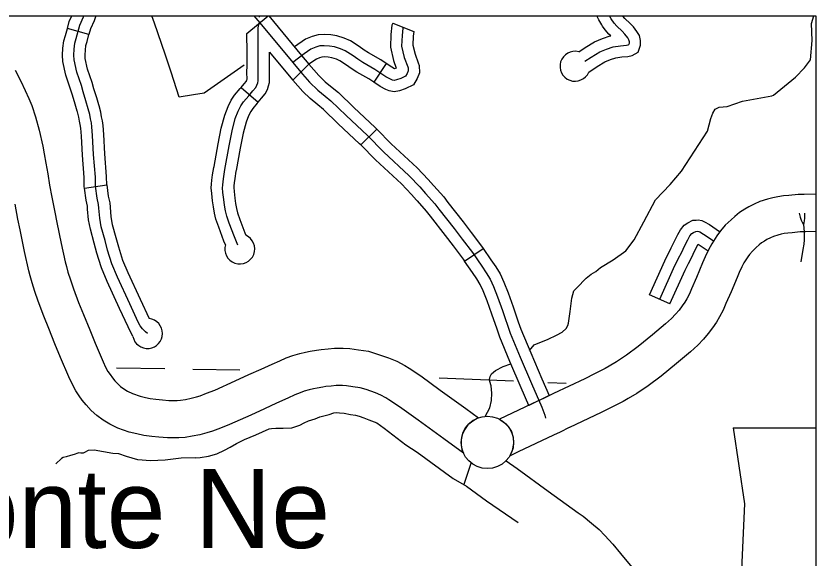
# Model space of a CAD drawing. Extents: x 670147 to 673275, y 705573 to 707613.
# Drawn here: x 672115.2 to 672221.9, y 706616.9 to 706689.4 of the extents above; entities that cross this region are included whole.
import ezdxf

# ---------------------------------------------------------------- set-up
doc = ezdxf.new("R2010")
doc.units = 0
for name, color, linetype in [('10', 7, 'Continuous'), ('21', 7, 'Continuous'), ('24', 7, 'Continuous'), ('31', 7, 'Continuous'), ('32', 7, 'Continuous'), ('33', 7, 'Continuous'), ('35', 7, 'Continuous'), ('5', 7, 'Continuous'), ('6', 7, 'Continuous'), ('R_NoPlot', 7, 'Continuous')]:
    doc.layers.add(name, color=color, linetype=linetype)

msp = doc.modelspace()

# ---------------------------------------------------------------- linework, layer by layer
at = {"layer": '10'}
msp.add_line((672186.91, 706638.92), (672186.89, 706638.91), dxfattribs=at)
for points in [[(672115.05, 706682.13), (672115.81, 706680.63), (672116.4, 706679.41), (672116.86, 706678.32), (672117.25, 706677.39), (672117.76, 706675.89), (672118.25, 706674.09), (672118.73, 706671.95), (672118.91, 706670.94), (672119.14, 706669.67), (672119.4, 706668.25), (672119.65, 706666.75), (672119.96, 706665.16), (672120.33, 706663.15), (672120.61, 706661.76), (672121.17, 706658.94), (672121.74, 706656.49), (672121.88, 706655.9), (672122.09, 706655.14), (672122.43, 706654.12), (672122.84, 706652.9), (672123.52, 706651.06), (672124.16, 706649.46), (672124.99, 706647.44), (672125.72, 706645.64), (672126.78, 706643.16), (672127.11, 706642.45), (672127.43, 706641.87), (672127.72, 706641.44), (672128.03, 706641), (672128.33, 706640.62), (672128.69, 706640.23), (672129.1, 706639.86), (672129.54, 706639.53), (672130.05, 706639.23), (672130.7, 706638.92), (672131.71, 706638.55), (672132.44, 706638.37), (672133.05, 706638.23), (672133.83, 706638.14), (672134.69, 706638.05), (672135.56, 706637.98), (672136.66, 706637.98), (672137.12, 706638.02), (672137.79, 706638.12), (672138.52, 706638.28), (672139.27, 706638.47), (672139.76, 706638.62), (672140.6, 706638.94), (672141.68, 706639.38), (672144.43, 706640.6), (672146.25, 706641.43), (672147.87, 706642.16), (672149.37, 706642.84), (672150.37, 706643.3), (672151.23, 706643.67), (672152.09, 706643.98), (672153.05, 706644.25), (672153.79, 706644.42), (672154.42, 706644.56), (672155.26, 706644.7), (672155.88, 706644.8), (672156.8, 706644.88), (672157.66, 706644.95), (672158.82, 706644.97), (672159.71, 706644.93), (672160.88, 706644.77), (672162.21, 706644.55), (672163.42, 706644.19), (672164.88, 706643.67), (672165.97, 706643.24), (672167.06, 706642.64), (672167.62, 706642.29), (672169.19, 706641.26), (672171.77, 706639.38), (672175.18, 706636.89), (672176.88, 706635.67), (672176.16, 706635.32), (672175.48, 706634.74), (672175.01, 706634.08), (672174.69, 706633.4), (672174.58, 706632.74), (672174.58, 706632.04), (672174.67, 706631.42), (672174.87, 706630.96)], [(672221.93, 706665.57), (672220.35, 706665.51), (672219.55, 706665.49), (672218.3, 706665.38), (672217.58, 706665.32), (672216.82, 706665.21), (672216.15, 706665.07), (672215.44, 706664.88), (672214.43, 706664.55), (672213.67, 706664.21), (672212.97, 706663.84), (672212.44, 706663.53), (672211.72, 706663.09), (672211.1, 706662.55), (672210.6, 706662.13), (672209.83, 706661.39), (672209.17, 706660.63), (672208.7, 706660), (672208.01, 706658.9), (672207.57, 706658.1), (672207.13, 706657.17), (672206.78, 706656.37), (672205.98, 706654.43), (672205.33, 706652.92), (672205.03, 706652.22), (672204.68, 706651.57), (672204.42, 706651.13), (672204.07, 706650.63), (672203.65, 706650.07), (672203.18, 706649.52), (672202.63, 706648.94), (672201.85, 706648.21), (672200.13, 706646.77), (672198.19, 706645.19), (672196.63, 706644.02), (672195.32, 706643.14), (672194.32, 706642.55), (672193.8, 706642.24), (672192.37, 706641.53), (672191.06, 706640.86), (672186.91, 706638.92)], [(672174.87, 706630.96), (672172.25, 706632.84), (672168.82, 706635.35), (672166.35, 706637.15), (672164.92, 706638.08), (672164.53, 706638.33), (672163.83, 706638.71), (672163.12, 706638.99), (672161.88, 706639.43), (672161.08, 706639.67), (672160.13, 706639.82), (672159.25, 706639.95), (672158.74, 706639.97), (672157.9, 706639.96), (672157.22, 706639.9), (672156.51, 706639.84), (672156.09, 706639.77), (672155.36, 706639.64), (672154.86, 706639.54), (672154.29, 706639.41), (672153.63, 706639.22), (672153.07, 706639.02), (672152.39, 706638.72), (672151.44, 706638.29), (672149.94, 706637.61), (672148.32, 706636.87), (672146.48, 706636.04), (672143.64, 706634.78), (672142.44, 706634.29), (672141.37, 706633.89), (672140.63, 706633.66), (672139.68, 706633.41), (672138.69, 706633.2), (672137.72, 706633.05), (672136.87, 706632.98), (672135.36, 706632.98), (672134.24, 706633.07), (672133.28, 706633.17), (672132.2, 706633.3), (672131.27, 706633.51), (672130.25, 706633.76), (672128.75, 706634.3), (672127.68, 706634.82), (672126.77, 706635.36), (672125.95, 706635.98), (672125.18, 706636.65), (672124.51, 706637.38), (672124.01, 706638.02), (672123.61, 706638.59), (672123.16, 706639.26), (672122.64, 706640.2), (672122.21, 706641.13), (672121.11, 706643.72), (672120.36, 706645.55), (672119.53, 706647.59), (672118.86, 706649.26), (672118.13, 706651.23), (672117.68, 706652.55), (672117.31, 706653.69), (672117.05, 706654.63), (672116.88, 706655.32), (672116.28, 706657.89), (672115.7, 706660.79), (672115.42, 706662.2), (672115.04, 706664.23)], [(672221.93, 706660.56), (672220.51, 706660.52), (672219.83, 706660.5), (672218.73, 706660.4), (672218.16, 706660.35), (672217.7, 706660.28), (672217.3, 706660.2), (672216.86, 706660.09), (672216.25, 706659.88), (672215.84, 706659.7), (672215.39, 706659.47), (672215.04, 706659.25), (672214.68, 706659.03), (672214.36, 706658.76), (672213.96, 706658.42), (672213.45, 706657.93), (672213.07, 706657.49), (672212.83, 706657.17), (672212.32, 706656.36), (672212.02, 706655.82), (672211.68, 706655.1), (672211.39, 706654.42), (672210.59, 706652.49), (672209.92, 706650.93), (672209.53, 706650.04), (672209.05, 706649.15), (672208.64, 706648.43), (672208.1, 706647.67), (672207.55, 706646.94), (672206.9, 706646.17), (672206.15, 706645.39), (672205.18, 706644.47), (672203.31, 706642.91), (672201.27, 706641.25), (672199.53, 706639.95), (672198, 706638.92), (672196.87, 706638.25), (672196.18, 706637.84), (672194.61, 706637.06), (672193.26, 706636.37), (672189.03, 706634.39)], [(672186.89, 706638.91), (672185.63, 706638.31), (672184.76, 706637.88), (672179.68, 706635.48), (672180.36, 706635), (672180.84, 706634.52), (672181.28, 706633.83), (672181.52, 706633.05), (672181.58, 706632.23), (672181.4, 706631.3), (672181.07, 706630.58)], [(672181.07, 706630.58), (672182.24, 706631.16), (672186.92, 706633.37), (672187.81, 706633.81), (672189.05, 706634.4)], [(672180.57, 706629.93), (672182.03, 706628.88), (672186.19, 706625.85), (672190.19, 706622.97), (672190.87, 706622.51), (672191.98, 706621.6), (672192.99, 706620.73), (672193.76, 706619.94), (672194.8, 706618.79), (672195.84, 706617.54), (672197.36, 706615.72)]]:
    msp.add_lwpolyline(points, dxfattribs=at)
at = {"layer": '21'}
for p, q in [((672210.86, 706634.34), (672212.38, 706624.19)), ((672212.38, 706624.19), (672211.71, 706608.8))]:
    msp.add_line(p, q, dxfattribs=at)
msp.add_lwpolyline([(672210.86, 706634.34), (672221.93, 706634.34)], dxfattribs=at)
at = {"layer": '24'}
msp.add_circle((672178.07, 706632.38), 3.5, dxfattribs=at)
at = {"layer": '31'}
for p, q in [((672145.97, 706687), (672148.83, 706689.36)), ((672124.9, 706686.89), (672122.01, 706687.68)), ((672152.12, 706680.77), (672154.25, 706682.9)), ((672145.2, 706679.81), (672147.46, 706677.84)), ((672163.31, 706674.24), (672161.19, 706672.12)), ((672124.29, 706666.37), (672127.27, 706666.78)), ((672124.29, 706666.37), (672124.29, 706666.37)), ((672175.03, 706656.6), (672177.5, 706658.29))]:
    msp.add_line(p, q, dxfattribs=at)
for points in [[(672122.01, 706687.68), (672122.26, 706688.62), (672122.59, 706689.36)], [(672132.71, 706646.93), (672132.43, 706647.15), (672132.04, 706647.56), (672131.72, 706647.95), (672131.48, 706648.45), (672130.36, 706650.89), (672128.71, 706654.46), (672127.97, 706656.22), (672127.38, 706658.07), (672127.04, 706659.37), (672126.54, 706661.18), (672126.34, 706662.33), (672126.21, 706663.68), (672126.18, 706664.16), (672125.99, 706665.01), (672125.77, 706666.64), (672125.75, 706667.83), (672125.51, 706670.87), (672125.38, 706673.4), (672125.29, 706674.55), (672125.22, 706675.1), (672125.11, 706675.6), (672125.01, 706676.18), (672124.81, 706676.94), (672124.5, 706678.01), (672124.13, 706679.21), (672123.88, 706680.05), (672123.27, 706681.87), (672122.92, 706683.48), (672122.89, 706684.14), (672122.92, 706684.92), (672123.02, 706685.73), (672123.2, 706686.34), (672123.68, 706688.12), (672124.18, 706689.25), (672124.22, 706689.36)], [(672125.8, 706689.36), (672125.58, 706688.71), (672125.1, 706687.62), (672124.9, 706686.89)], [(672148.9, 706689.36), (672153.25, 706684.1), (672154.25, 706682.9)], [(672191.1, 706683.32), (672191.91, 706683.86), (672193.07, 706684.55), (672193.98, 706684.94), (672194.84, 706685.24), (672195.85, 706685.38), (672196.62, 706685.44), (672196.87, 706685.49), (672196.97, 706685.54), (672197.03, 706685.72), (672197.03, 706685.92), (672196.97, 706686.16), (672196.8, 706686.44), (672196.4, 706686.94), (672196.07, 706687.34), (672195.36, 706687.99), (672194.98, 706688.42), (672194.6, 706688.97), (672194.38, 706689.36)], [(672191.6, 706681.86), (672192.71, 706682.59), (672193.75, 706683.21), (672194.52, 706683.54), (672195.2, 706683.77), (672196.01, 706683.89), (672196.81, 706683.95), (672197.38, 706684.06), (672198.21, 706684.52), (672198.53, 706685.47), (672198.53, 706686.1), (672198.37, 706686.75), (672198.03, 706687.3), (672197.56, 706687.89), (672197.15, 706688.37), (672196.43, 706689.04), (672196.17, 706689.34), (672196.16, 706689.36)], [(672193.45, 706688), (672193.33, 706688.18), (672192.95, 706688.84), (672192.68, 706689.36)], [(672144.75, 706658.74), (672144.3, 706659.83), (672143.62, 706661.66), (672143.29, 706662.62), (672143.11, 706663.34), (672142.98, 706664.08), (672142.89, 706664.84), (672142.78, 706665.77), (672142.73, 706666.41), (672142.75, 706666.77), (672142.79, 706667.25), (672142.89, 706667.89), (672143.04, 706668.86), (672143.61, 706671.99), (672144.01, 706674.01), (672144.43, 706675.64), (672144.83, 706676.65), (672145.18, 706677.35), (672145.54, 706677.89), (672146.22, 706678.7), (672146.78, 706679.34), (672147.16, 706679.8), (672147.32, 706680.11), (672147.42, 706680.42), (672147.48, 706680.69), (672147.5, 706681.06), (672147.47, 706681.69), (672147.5, 706682.87), (672147.5, 706684.51), (672147.47, 706687.68), (672147.54, 706688.07), (672147.71, 706688.44)], [(672147.71, 706688.44), (672152.09, 706683.14), (672153.4, 706681.58), (672154.35, 706680.5), (672155.43, 706679.44), (672156.42, 706678.63), (672157.19, 706678), (672159.21, 706676.05), (672162.06, 706673.37), (672164.21, 706671.21), (672167.65, 706667.98), (672169.07, 706666.51), (672169.81, 706665.65), (672171.08, 706664.24), (672171.61, 706663.53), (672173.63, 706660.96), (672174.71, 706659.54), (672176.07, 706657.74), (672177.31, 706655.92), (672177.92, 706655.04), (672178.44, 706654.18), (672178.89, 706653.22), (672179.44, 706651.84), (672180.08, 706650), (672181.13, 706646.99), (672182.47, 706643.77), (672183.97, 706640.27), (672185.35, 706637.07), (672185.72, 706636.03), (672185.84, 706635.63)], [(672190.27, 706684.57), (672191.11, 706685.13), (672192.39, 706685.89), (672193.44, 706686.34), (672194.48, 706686.7), (672194.53, 706686.71), (672194.28, 706686.94), (672193.79, 706687.5), (672193.45, 706688)], [(672123.33, 706676.64), (672123.06, 706677.58), (672122.69, 706678.78), (672122.45, 706679.6), (672121.83, 706681.47), (672121.43, 706683.27), (672121.38, 706684.14), (672121.43, 706685.04), (672121.54, 706686.04), (672121.76, 706686.76), (672122.01, 706687.68)], [(672145.2, 706679.81), (672145.63, 706680.31), (672145.9, 706680.63), (672145.92, 706680.68), (672145.97, 706680.83), (672145.99, 706680.9), (672146, 706681.06), (672145.97, 706681.68), (672146, 706682.88), (672146, 706684.5), (672145.97, 706687)], [(672126.21, 706677.48), (672125.93, 706678.44), (672125.56, 706679.64), (672125.32, 706680.49), (672124.72, 706682.27), (672124.41, 706683.68), (672124.39, 706684.15), (672124.42, 706684.8), (672124.49, 706685.43), (672124.64, 706685.93), (672124.9, 706686.89)], [(672147.46, 706677.84), (672147.92, 706678.36), (672148.42, 706678.97), (672148.71, 706679.53), (672148.86, 706680.02), (672148.98, 706680.48), (672149, 706681.05), (672148.98, 706681.7), (672149, 706682.85), (672149, 706684.52)], [(672149, 706684.52), (672150.94, 706682.18), (672152.12, 706680.77)], [(672154.25, 706682.9), (672155.56, 706681.42), (672156.43, 706680.55), (672157.37, 706679.79), (672158.19, 706679.12), (672160.24, 706677.13), (672163.11, 706674.44), (672163.31, 706674.24)], [(672161.19, 706672.12), (672161.02, 706672.29), (672158.17, 706674.96), (672156.19, 706676.88), (672155.46, 706677.47), (672154.42, 706678.32), (672153.45, 706679.29), (672152.12, 706680.77)], [(672141.59, 706669.23), (672142.13, 706672.27), (672142.55, 706674.35), (672143.01, 706676.1), (672143.46, 706677.26), (672143.88, 706678.1), (672144.34, 706678.79), (672145.08, 706679.68), (672145.2, 706679.81)], [(672127.27, 706666.76), (672127.25, 706667.9), (672127.01, 706670.96), (672126.88, 706673.5), (672126.78, 706674.71), (672126.69, 706675.37), (672126.58, 706675.89), (672126.48, 706676.49), (672126.25, 706677.34), (672126.21, 706677.48)], [(672147.46, 706677.84), (672147.36, 706677.73), (672146.75, 706677), (672146.48, 706676.59), (672146.2, 706676.03), (672145.86, 706675.17), (672145.47, 706673.68), (672145.08, 706671.71), (672144.54, 706668.7)], [(672124.29, 706666.37), (672124.27, 706666.53), (672124.25, 706667.76), (672124.02, 706670.77), (672123.89, 706673.3), (672123.8, 706674.39), (672123.74, 706674.84), (672123.63, 706675.32), (672123.54, 706675.86), (672123.37, 706676.53), (672123.33, 706676.64)], [(672163.31, 706674.24), (672165.25, 706672.29), (672168.71, 706669.05), (672170.18, 706667.52), (672170.87, 706666.72)], [(672161.19, 706672.12), (672163.16, 706670.14), (672166.6, 706666.91), (672167.96, 706665.49), (672168.6, 706664.76)], [(672143.1, 706658.8), (672142.9, 706659.28), (672142.21, 706661.15), (672141.85, 706662.2), (672141.64, 706663.02), (672141.5, 706663.86), (672141.4, 706664.67), (672141.28, 706665.63), (672141.22, 706666.4), (672141.25, 706666.88), (672141.3, 706667.43), (672141.4, 706668.12), (672141.57, 706669.11), (672141.59, 706669.23)], [(672144.54, 706668.7), (672144.52, 706668.61), (672144.37, 706667.66), (672144.28, 706667.08), (672144.25, 706666.66), (672144.23, 706666.43), (672144.27, 706665.92), (672144.38, 706665.02), (672144.46, 706664.3), (672144.58, 706663.65), (672144.73, 706663.05), (672145.03, 706662.16), (672145.69, 706660.38), (672145.83, 706660.06)], [(672127.27, 706666.78), (672127.47, 706665.27), (672127.67, 706664.37), (672127.71, 706663.81), (672127.83, 706662.53), (672128.01, 706661.51), (672128.49, 706659.76), (672128.82, 706658.49), (672129.38, 706656.73)], [(672170.87, 706666.72), (672170.93, 706666.65), (672172.24, 706665.19), (672172.8, 706664.45), (672174.82, 706661.87), (672175.9, 706660.44), (672177.29, 706658.61), (672177.5, 706658.29)], [(672126.52, 706655.82), (672125.94, 706657.66), (672125.59, 706658.98), (672125.08, 706660.85), (672124.85, 706662.13), (672124.72, 706663.56), (672124.69, 706663.95), (672124.52, 706664.75), (672124.29, 706666.37)], [(672168.6, 706664.76), (672168.68, 706664.66), (672169.92, 706663.28), (672170.42, 706662.62), (672172.44, 706660.04), (672173.51, 706658.63), (672174.85, 706656.86), (672175.03, 706656.6)], [(672177.5, 706658.29), (672178.54, 706656.77), (672179.18, 706655.85), (672179.76, 706654.9), (672180.27, 706653.81), (672180.84, 706652.36), (672181.5, 706650.49), (672182.2, 706648.47)], [(672129.38, 706656.73), (672129.38, 706656.74), (672130.08, 706655.07), (672131.72, 706651.52), (672132.92, 706648.92)], [(672179.37, 706647.49), (672178.67, 706649.5), (672178.03, 706651.31), (672177.52, 706652.63), (672177.12, 706653.47), (672176.66, 706654.22), (672176.07, 706655.07), (672175.03, 706656.6)], [(672130.75, 706646.52), (672130.13, 706647.81), (672128.99, 706650.26), (672127.34, 706653.86), (672126.56, 706655.7), (672126.52, 706655.82)], [(672186.31, 706638.63), (672183.6, 706637.33), (672182.6, 706639.68), (672181.08, 706643.19), (672179.73, 706646.45), (672179.37, 706647.49)], [(672182.2, 706648.47), (672182.54, 706647.52), (672183.85, 706644.35), (672185.35, 706640.86), (672186.31, 706638.63)]]:
    msp.add_lwpolyline(points, dxfattribs=at)
for centre, start, end in [((672189.76, 706682.64), 75.34, 337.0929), ((672145.02, 706658.23), 163.4625, 66.1741), ((672132.71, 706646.93), 191.8762, 83.8651)]:
    msp.add_arc(centre, 2, start, end, dxfattribs=at)
at = {"layer": '32'}
for p, q in [((672165.45, 706688.42), (672168.25, 706687.29)), ((672164.58, 706683), (672162.9, 706680.51)), ((672167.44, 706682.57), (672167.49, 706682.42)), ((672202.44, 706650.88), (672199.71, 706652.11))]:
    msp.add_line(p, q, dxfattribs=at)
for points in [[(672165.45, 706688.42), (672165.32, 706688.11), (672165.19, 706686.88), (672165.12, 706685.2), (672165.53, 706683.4), (672165.91, 706682.39), (672165.69, 706682.31), (672165.31, 706682.51), (672164.58, 706683)], [(672168.25, 706687.29), (672168.18, 706686.65), (672168.14, 706685.48), (672168.42, 706684.25), (672168.85, 706683.09), (672168.97, 706682.73), (672169.03, 706681.77), (672168.7, 706680.99), (672168.2, 706680.17), (672167.11, 706679.63), (672166.35, 706679.36), (672165.61, 706679.23), (672164.96, 706679.36), (672164.5, 706679.55), (672163.77, 706679.93), (672162.9, 706680.51)], [(672166.84, 706687.86), (672166.79, 706687.74), (672166.68, 706686.77), (672166.63, 706685.34), (672166.98, 706683.83), (672167.44, 706682.57)], [(672164.58, 706683), (672163.85, 706683.49), (672162.22, 706684.42), (672161.62, 706684.81), (672160.98, 706685.28), (672159.79, 706686.03), (672158.97, 706686.39), (672157.99, 706686.69), (672157.18, 706686.82), (672156.33, 706686.89), (672155.49, 706686.84), (672154.68, 706686.62), (672153.8, 706686.25), (672152.31, 706685.23)], [(672167.49, 706682.42), (672167.51, 706682.03), (672167.37, 706681.68), (672167.15, 706681.32), (672166.53, 706681.02), (672165.96, 706680.81), (672165.63, 706680.75), (672165.4, 706680.8), (672165.13, 706680.91), (672164.54, 706681.22), (672163.06, 706682.22), (672161.44, 706683.14), (672160.76, 706683.58), (672160.14, 706684.04), (672159.08, 706684.7), (672158.45, 706684.99), (672157.65, 706685.22), (672157, 706685.33), (672156.31, 706685.38), (672155.72, 706685.35), (672155.17, 706685.2), (672154.52, 706684.93), (672153.6, 706684.29), (672152.09, 706683.14)], [(672162.9, 706680.51), (672162.27, 706680.94), (672160.66, 706681.85), (672159.9, 706682.35), (672159.29, 706682.8), (672158.37, 706683.37), (672157.92, 706683.58), (672157.32, 706683.76), (672156.83, 706683.84), (672156.29, 706683.88), (672155.96, 706683.86), (672155.65, 706683.78), (672155.25, 706683.61), (672154.26, 706682.9)], [(672219.69, 706662.99), (672219.84, 706662.48), (672219.96, 706662.08), (672220.03, 706661.9), (672220.12, 706661.7), (672220.27, 706661.48), (672220.34, 706661.7), (672220.41, 706662), (672220.44, 706662.34), (672220.45, 706662.65), (672220.43, 706663.01)], [(672199.71, 706652.11), (672201.74, 706656.65), (672202.06, 706657.3), (672202.27, 706657.69), (672202.62, 706658.37), (672203.08, 706659.36), (672203.49, 706660.14), (672203.85, 706660.79), (672204.34, 706661.4), (672204.82, 706661.74), (672205.51, 706662.06), (672205.96, 706662.08)], [(672205.96, 706662.08), (672206.19, 706662.1), (672206.69, 706662.02), (672207.07, 706661.86), (672207.73, 706661.49), (672209.06, 706660.57)], [(672220.27, 706661.48), (672220.37, 706660.5), (672220.37, 706659.91), (672220.36, 706659.43), (672220.3, 706658.87), (672220.19, 706658.15), (672219.89, 706656.5)], [(672201.07, 706651.5), (672203.1, 706656.01), (672203.39, 706656.61), (672203.6, 706656.98), (672203.97, 706657.72), (672204.43, 706658.7), (672204.81, 706659.43), (672205.11, 706659.96), (672205.38, 706660.3), (672205.57, 706660.44), (672205.88, 706660.58), (672206.11, 706660.59), (672206.28, 706660.56), (672206.42, 706660.51), (672206.93, 706660.22), (672208.21, 706659.34)], [(672202.44, 706650.88), (672204.46, 706655.38), (672204.72, 706655.92), (672204.92, 706656.28), (672205.32, 706657.06), (672205.77, 706658.03), (672206.22, 706658.88)], [(672206.22, 706658.88), (672207.52, 706657.99)]]:
    msp.add_lwpolyline(points, dxfattribs=at)
at = {"layer": '33'}
msp.add_lwpolyline([(672146.89, 706689.36), (672147.71, 706688.44)], dxfattribs=at)
at = {"layer": '35'}
for points in [[(672216.05, 706678.67), (672216.27, 706678.79), (672219.2, 706681.19), (672220.38, 706682.42), (672221.18, 706683.49), (672221.44, 706686.1), (672221.34, 706688.34), (672221.63, 706689.36)], [(672198.97, 706661.84), (672200.51, 706664.8), (672202.48, 706666.82), (672203.98, 706668.64), (672206.29, 706672.19), (672207.47, 706673.96), (672207.9, 706675.67), (672208.17, 706676.36), (672208.49, 706676.89), (672208.81, 706677.08), (672209.02, 706677.16), (672210.09, 706677.27), (672212.12, 706677.96), (672216.05, 706678.67)], [(672183.71, 706644.67), (672184.33, 706645.41), (672186.2, 706646.19), (672187.31, 706646.72), (672188.06, 706647.1), (672188.59, 706647.58), (672188.81, 706647.98), (672188.88, 706648.3), (672189.12, 706649.89), (672189.33, 706651.63), (672189.6, 706652.62), (672190, 706653.03), (672191.24, 706654.32), (672191.91, 706654.85), (672192.54, 706655.23), (672193.18, 706655.75), (672194.86, 706656.77), (672196.53, 706657.96), (672197.66, 706659.43), (672198.97, 706661.84)], [(672177.79, 706635.86), (672178.42, 706636.99), (672178.6, 706637.97), (672178.68, 706638.96), (672178.59, 706639.93), (672178.39, 706640.52), (672178.37, 706640.77), (672178.44, 706641.18), (672178.62, 706641.53), (672179.14, 706641.98), (672180.2, 706642.54), (672181.22, 706642.88)], [(672139.15, 706630.31), (672139.75, 706630.36), (672140.84, 706630.52), (672141.97, 706630.87), (672142.98, 706631.33), (672143.73, 706631.74), (672144.59, 706632.23), (672145.67, 706632.78), (672147.19, 706633.41), (672148.94, 706634.18), (672149.24, 706634.23), (672149.85, 706634.27), (672150.8, 706634.27), (672151.97, 706634.33), (672153.02, 706634.7), (672153.63, 706634.99), (672154.2, 706635.28), (672155.09, 706635.55), (672155.72, 706635.78), (672156.95, 706636.11), (672157.56, 706636.32), (672157.87, 706636.37), (672158.33, 706636.33), (672158.95, 706636.29), (672159.8, 706636.12), (672160.47, 706636.03), (672160.95, 706635.9), (672161.57, 706635.66), (672162.23, 706635.41), (672163.3, 706634.99), (672164.28, 706634.28), (672167.19, 706632.06), (672168.72, 706631.09), (672173.52, 706627.54), (672175.29, 706626.55), (672177.94, 706624.59), (672182.16, 706621.69)], [(672128.08, 706630.89), (672125.58, 706631.36), (672124.77, 706631.28), (672124.3, 706631.03), (672124.11, 706630.93), (672123.83, 706630.92), (672123.52, 706630.97), (672123.39, 706630.93), (672122.92, 706630.74), (672122.45, 706630.64), (672121.85, 706630.46), (672121.46, 706630.37), (672121.21, 706630.22), (672120.46, 706629.51)], [(672139.15, 706630.31), (672137.21, 706630.25), (672135.05, 706629.99), (672133.11, 706629.93), (672131.44, 706630.07), (672129.91, 706630.48), (672128.87, 706630.87), (672128.08, 706630.89)], [(672174.98, 706626.78), (672175.92, 706629.61)]]:
    msp.add_lwpolyline(points, dxfattribs=at)
at = {"layer": '5'}
for points in [[(672135.02, 706642.19), (672128.57, 706642.3)], [(672145.04, 706642.02), (672138.76, 706642.13)], [(672181.58, 706640.55), (672171.63, 706640.97)], [(672188.57, 706640.25), (672186.14, 706640.35)]]:
    msp.add_lwpolyline(points, dxfattribs=at)
at = {"layer": '6'}
for points in [[(672145.63, 706682.79), (672140.26, 706679.06), (672138.85, 706678.83), (672136.95, 706678.51), (672135.88, 706681.83), (672135.06, 706684.24), (672133.65, 706688.39), (672133.3, 706689.36)], [(672147.62, 706689.36), (672147.62, 706689.22)]]:
    msp.add_lwpolyline(points, dxfattribs=at)
at = {"layer": 'R_NoPlot'}
msp.add_lwpolyline([(671149.93, 706689.36), (672221.93, 706689.36), (672221.93, 705919.71), (671149.93, 705919.71)], close=True, dxfattribs=at)

# ---------------------------------------------------------------- texts
at = {"layer": '24'}
msp.add_text('Monte Ne', height=10.56, dxfattribs=at).set_placement((672095.87, 706618.27))

doc.saveas('drawing.dxf')
